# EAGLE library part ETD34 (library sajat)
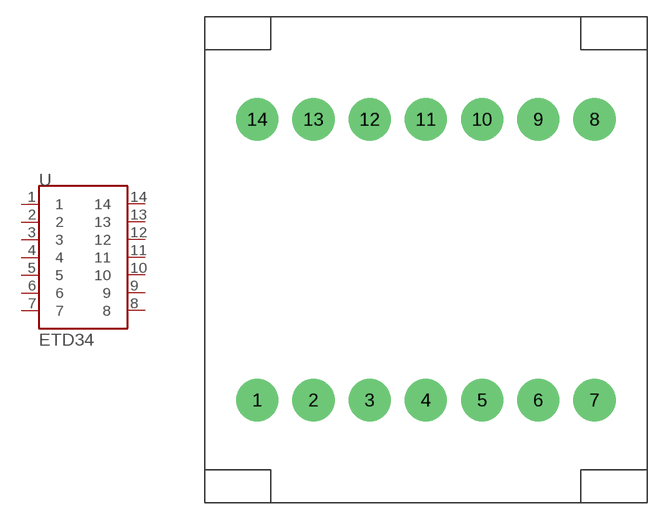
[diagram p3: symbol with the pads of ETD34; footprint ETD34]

Designator prefix -

## ETD34  [ETD34]
1  1
2  2
3  3
4  4
5  5
6  6
7  7
8  8
9  9
10  10
11  11
12  12
13  13
14  14

## Footprint ETD34 (pad centres in mm)
drill 0.6 pad 3.81 round: 1 -15.24,-12.7; 2 -10.16,-12.7; 3 -5.08,-12.7; 4 0,-12.7; 5 5.08,-12.7; 6 10.16,-12.7; 7 15.24,-12.7; 8 15.24,12.7; 9 10.16,12.7; 10 5.08,12.7; 11 0,12.7; 12 -5.08,12.7; 13 -10.16,12.7; 14 -15.24,12.7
